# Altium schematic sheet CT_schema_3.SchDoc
size 294 x 159 mm
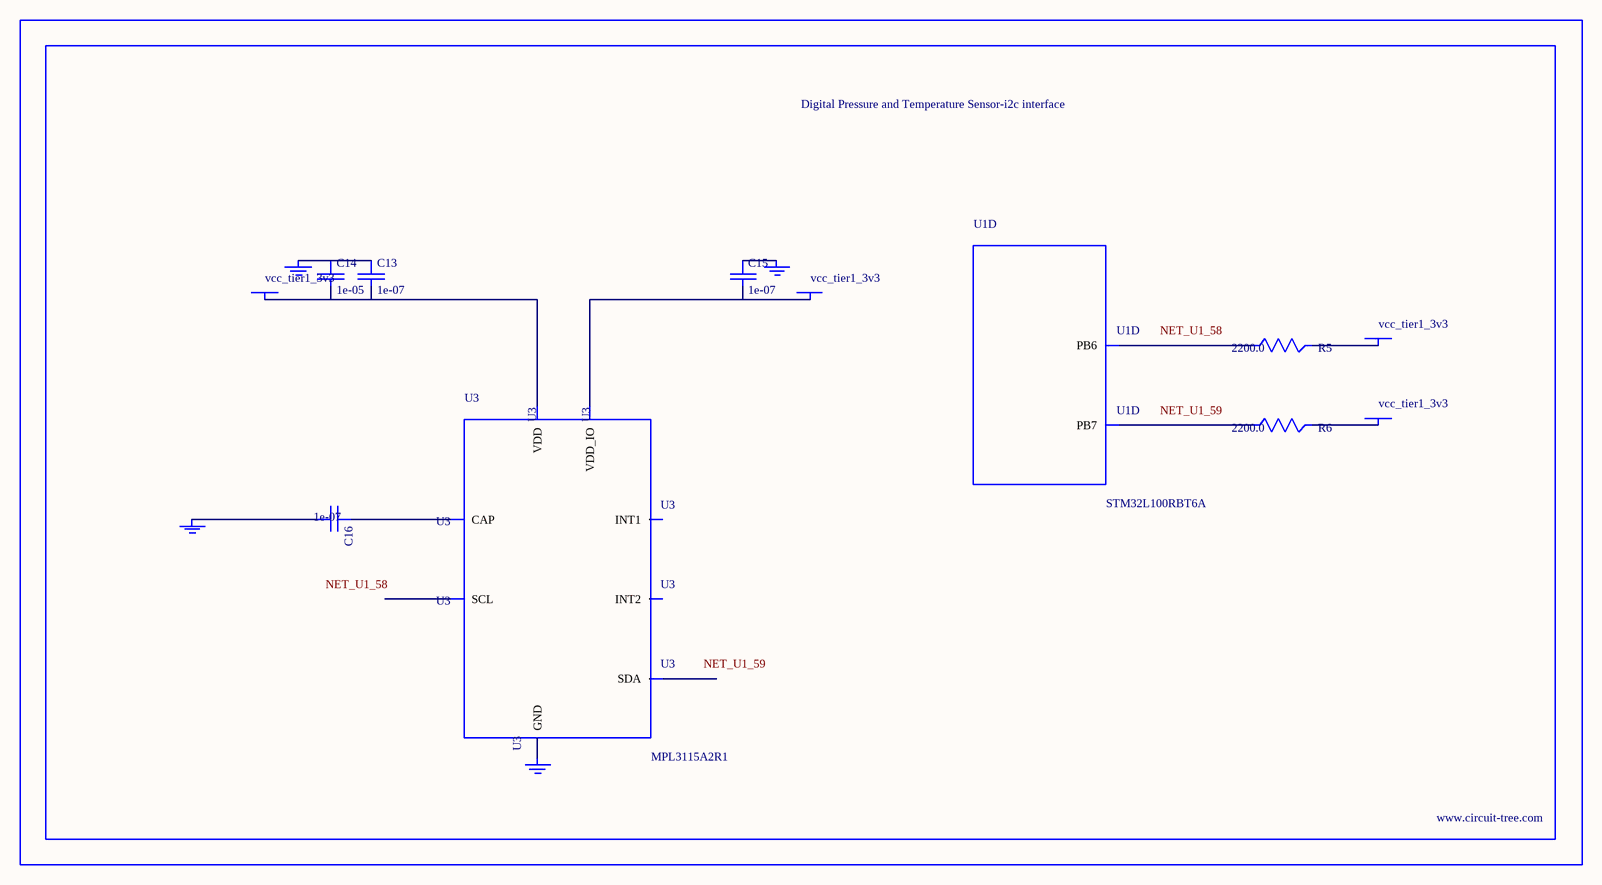
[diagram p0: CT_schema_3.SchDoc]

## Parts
BORDER2  (no value)
C13  1e-07  [C0402]
C14  1e-05  [C0805]
C15  1e-07  [C0402]
C16  1e-07  [C0402]
GND_INSTANCE_2_0  (no value)
GND_INSTANCE_2_1  (no value)
GND_INSTANCE_2_2  (no value)
GND_INSTANCE_2_3  (no value)
POWER_INSTANCE_2_0  vcc_tier1_3v3
POWER_INSTANCE_2_1  vcc_tier1_3v3
POWER_INSTANCE_2_2  vcc_tier1_3v3
POWER_INSTANCE_2_3  vcc_tier1_3v3
R5  2200.0  [R0603]
R6  2200.0  [R0603]
U1  STM32L100RBT6A  [LQFP64]  (part D of 7)
U3  MPL3115A2R1  [LGA-8]

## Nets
NetC13_1: C13.1 C14.1 GND_INSTANCE_2_0.0(GND)
NetC13_2: C13.2 C14.2 POWER_INSTANCE_2_0.0(PWR) U3.1(VDD)
NetC15_1: C15.1 GND_INSTANCE_2_2.0(GND)
NetC15_2: C15.2 POWER_INSTANCE_2_1.0(PWR) U3.4(VDD_IO)
NetC16_1: C16.1 U3.2(CAP)
NetC16_2: C16.2 GND_INSTANCE_2_1.0(GND)
NetGND_INSTANCE_2_3_0: GND_INSTANCE_2_3.0(GND) U3.3(GND)
NetPOWER_INSTANCE_2_2_0: POWER_INSTANCE_2_2.0(PWR) R5.2
NetPOWER_INSTANCE_2_3_0: POWER_INSTANCE_2_3.0(PWR) R6.2
NetR5_1: R5.1 U1.58(PB6)
NetR6_1: R6.1 U1.59(PB7)

Not connected (* = marked no-connect by the designer): U3 5(INT2) 6(INT1) 7(SDA) 8(SCL)

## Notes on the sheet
- Labels drawn without touching a wire or pin: NET_U1_58, NET_U1_59

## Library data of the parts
BORDER2 = BORDER_PAGE2
C13 C15 C16 = C0402C104K3RACTU
C14 = C0805C106K8RACTU
GND_INSTANCE_2_0-GND_INSTANCE_2_3 = GND
POWER_INSTANCE_2_0-POWER_INSTANCE_2_3 = PWR
R5 R6 = RC0603JR-072K2L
